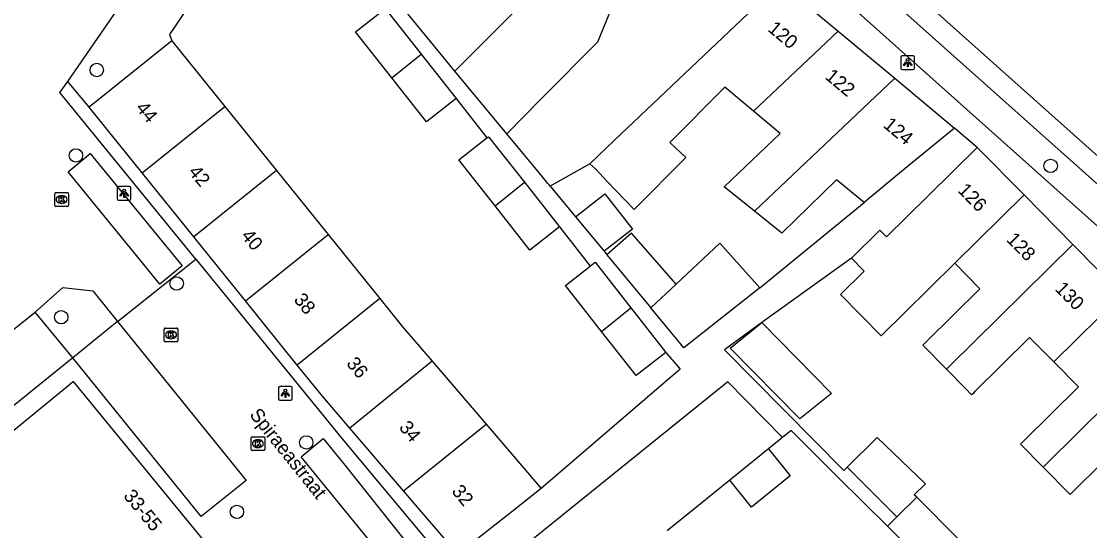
# Model space of a CAD drawing. Extents: x 161882 to 162509, y 381687 to 382379.
# Drawn here: x 162177.6 to 162255.4, y 382032.1 to 382069.2 of the extents above; entities that cross this region are included whole.
import ezdxf

# ---------------------------------------------------------------- set-up
doc = ezdxf.new("R2010")
doc.units = 0
for name, color, linetype in [('IMGEO_Boom', 7, 'Continuous'), ('IMGEO_Haag', 7, 'Continuous'), ('IMGEO_Kolk', 7, 'Continuous'), ('IMGEO_Lichtpunt', 7, 'Continuous'), ('IMGEO_Openbare_ruimte_label', 7, 'Continuous'), ('IMGEO_Pand', 7, 'Continuous'), ('IMGEO_Pand_nummerreeks', 7, 'Continuous'), ('IMGEO_Parkeervlak_open', 7, 'Continuous'), ('IMGEO_Rijbaan_lokaal_gesloten', 7, 'Continuous'), ('IMGEO_Rijbaan_lokaal_open', 7, 'Continuous'), ('IMGEO_Voetpad_open', 7, 'Continuous'), ('IMGEO_Woonerf_open', 7, 'Continuous')]:
    doc.layers.add(name, color=color, linetype=linetype)

msp = doc.modelspace()

# ---------------------------------------------------------------- linework, layer by layer
at = {"layer": 'IMGEO_Boom'}
for centre in [(162183.068, 382065.693), (162181.549, 382059.465), (162252.559, 382058.707), (162188.889, 382050.134), (162180.48, 382047.676), (162198.331, 382038.553), (162193.28, 382033.486)]:
    msp.add_circle(centre, 0.489, dxfattribs=at)
at = {"layer": 'IMGEO_Haag'}
for points in [[(162192.04, 382073.726), (162188.366, 382068.285), (162188.533, 382067.832)], [(162182.522, 382062.989), (162180.952, 382064.864)]]:
    msp.add_lwpolyline(points, dxfattribs=at)
at = {"layer": 'IMGEO_Kolk'}
for p, q in [((162180.005, 382055.829), (162180.005, 382056.681)), ((162180.08, 382056.755), (162180.932, 382056.755)), ((162180.493, 382056.535), (162180.518, 382056.535)), ((162181.006, 382056.681), (162181.006, 382055.829)), ((162180.932, 382055.755), (162180.08, 382055.755)), ((162180.516, 382055.975), (162180.491, 382055.975)), ((162187.978, 382045.964), (162187.978, 382046.816)), ((162188.053, 382046.89), (162188.905, 382046.89)), ((162188.466, 382046.67), (162188.491, 382046.67)), ((162188.979, 382046.816), (162188.979, 382045.964)), ((162188.905, 382045.89), (162188.053, 382045.89)), ((162188.489, 382046.11), (162188.464, 382046.11)), ((162194.307, 382038.036), (162194.307, 382038.888)), ((162194.382, 382038.962), (162195.234, 382038.962)), ((162194.795, 382038.742), (162194.82, 382038.742)), ((162195.308, 382038.888), (162195.308, 382038.036)), ((162195.234, 382037.962), (162194.382, 382037.962)), ((162194.818, 382038.182), (162194.793, 382038.182))]:
    msp.add_line(p, q, dxfattribs=at)
for points in [[(162180.005, 382055.829), (162180.005, 382056.681)], [(162180.08, 382056.755), (162180.932, 382056.755)], [(162180.326, 382056.455), (162180.449, 382056.455), (162180.449, 382056.304), (162180.579, 382056.455), (162180.743, 382056.455), (162180.597, 382056.304), (162180.75, 382056.055), (162180.598, 382056.055), (162180.513, 382056.219), (162180.449, 382056.152), (162180.449, 382056.055), (162180.326, 382056.055), (162180.326, 382056.455)], [(162181.006, 382056.681), (162181.006, 382055.829)], [(162180.932, 382055.755), (162180.08, 382055.755)], [(162187.978, 382045.964), (162187.978, 382046.816)], [(162188.053, 382046.89), (162188.905, 382046.89)], [(162188.299, 382046.59), (162188.422, 382046.59), (162188.422, 382046.439), (162188.552, 382046.59), (162188.716, 382046.59), (162188.57, 382046.439), (162188.723, 382046.19), (162188.571, 382046.19), (162188.486, 382046.354), (162188.422, 382046.287), (162188.422, 382046.19), (162188.299, 382046.19), (162188.299, 382046.59)], [(162188.979, 382046.816), (162188.979, 382045.964)], [(162188.905, 382045.89), (162188.053, 382045.89)], [(162194.307, 382038.036), (162194.307, 382038.888)], [(162194.382, 382038.962), (162195.234, 382038.962)], [(162194.628, 382038.662), (162194.751, 382038.662), (162194.751, 382038.511), (162194.881, 382038.662), (162195.045, 382038.662), (162194.899, 382038.511), (162195.052, 382038.262), (162194.9, 382038.262), (162194.815, 382038.426), (162194.751, 382038.359), (162194.751, 382038.262), (162194.628, 382038.262), (162194.628, 382038.662)], [(162195.308, 382038.888), (162195.308, 382038.036)], [(162195.234, 382037.962), (162194.382, 382037.962)]]:
    msp.add_lwpolyline(points, dxfattribs=at)
for centre, start, end in [((162180.082, 382056.679), 91.55205, 178.44795), ((162180.082, 382056.679), 91.55205, 178.44795), ((162180.93, 382056.679), 1.55205, 88.44795), ((162180.93, 382056.679), 1.55205, 88.44795), ((162180.082, 382055.831), 181.55205, 268.44795), ((162180.082, 382055.831), 181.55205, 268.44795), ((162180.93, 382055.831), 271.55205, 358.44795), ((162180.93, 382055.831), 271.55205, 358.44795), ((162188.055, 382046.814), 91.55205, 178.44795), ((162188.055, 382046.814), 91.55205, 178.44795), ((162188.903, 382046.814), 1.55205, 88.44795), ((162188.903, 382046.814), 1.55205, 88.44795), ((162188.055, 382045.966), 181.55205, 268.44795), ((162188.055, 382045.966), 181.55205, 268.44795), ((162188.903, 382045.966), 271.55205, 358.44795), ((162188.903, 382045.966), 271.55205, 358.44795), ((162194.384, 382038.886), 91.55205, 178.44795), ((162194.384, 382038.886), 91.55205, 178.44795), ((162195.232, 382038.886), 1.55205, 88.44795), ((162195.232, 382038.886), 1.55205, 88.44795), ((162194.384, 382038.038), 181.55205, 268.44795), ((162194.384, 382038.038), 181.55205, 268.44795), ((162195.232, 382038.038), 271.55205, 358.44795), ((162195.232, 382038.038), 271.55205, 358.44795)]:
    msp.add_arc(centre, 0.0765, start, end, dxfattribs=at)
for centre, major_axis, ratio, start_param, end_param in [((162180.492, 382056.255), (-0.387, 0.002), 0.722429, 4.712389, 7.853982), ((162180.517, 382056.255), (-0.39, 0.002), 0.717154, 1.570796, 4.712389), ((162188.465, 382046.39), (-0.387, 0.002), 0.722429, 4.712389, 7.853982), ((162188.49, 382046.39), (-0.39, 0.002), 0.717154, 1.570796, 4.712389), ((162194.794, 382038.462), (-0.387, 0.002), 0.722429, 4.712389, 7.853982), ((162194.819, 382038.462), (-0.39, 0.002), 0.717154, 1.570796, 4.712389)]:
    msp.add_ellipse(centre, major_axis=major_axis, ratio=ratio, start_param=start_param, end_param=end_param, dxfattribs=at)
at = {"layer": 'IMGEO_Lichtpunt'}
for p, q in [((162241.646, 382066.636), (162241.646, 382065.829)), ((162241.646, 382066.636), (162241.646, 382065.829)), ((162242.548, 382066.731), (162241.74, 382066.731)), ((162242.548, 382066.731), (162241.74, 382066.731)), ((162242.642, 382065.829), (162242.642, 382066.636)), ((162242.642, 382065.829), (162242.642, 382066.636)), ((162241.74, 382065.735), (162242.548, 382065.735)), ((162241.74, 382065.735), (162242.548, 382065.735)), ((162184.562, 382057.119), (162184.562, 382056.312)), ((162184.562, 382057.119), (162184.562, 382056.312)), ((162185.464, 382057.214), (162184.656, 382057.214)), ((162185.464, 382057.214), (162184.656, 382057.214)), ((162185.558, 382056.312), (162185.558, 382057.119)), ((162185.558, 382056.312), (162185.558, 382057.119)), ((162184.656, 382056.218), (162185.464, 382056.218)), ((162184.656, 382056.218), (162185.464, 382056.218)), ((162196.307, 382042.538), (162196.307, 382041.731)), ((162196.307, 382042.538), (162196.307, 382041.731)), ((162197.209, 382042.633), (162196.401, 382042.633)), ((162197.209, 382042.633), (162196.401, 382042.633)), ((162197.303, 382041.731), (162197.303, 382042.538)), ((162197.303, 382041.731), (162197.303, 382042.538)), ((162196.401, 382041.637), (162197.209, 382041.637)), ((162196.401, 382041.637), (162197.209, 382041.637))]:
    msp.add_line(p, q, dxfattribs=at)
for points in [[(162242.02, 382066.3), (162242.059, 382066.272), (162241.871, 382066.01), (162241.833, 382066.037), (162242.02, 382066.3)], [(162242.122, 382066.252), (162242.169, 382066.252), (162242.169, 382065.93), (162242.122, 382065.93), (162242.122, 382066.252)], [(162242.232, 382066.272), (162242.27, 382066.299), (162242.457, 382066.037), (162242.418, 382066.009), (162242.232, 382066.272)], [(162184.936, 382056.783), (162184.975, 382056.755), (162184.787, 382056.493), (162184.749, 382056.52), (162184.936, 382056.783)], [(162185.038, 382056.735), (162185.085, 382056.735), (162185.085, 382056.413), (162185.038, 382056.413), (162185.038, 382056.735)], [(162185.148, 382056.755), (162185.186, 382056.782), (162185.373, 382056.52), (162185.334, 382056.492), (162185.148, 382056.755)], [(162196.681, 382042.202), (162196.72, 382042.174), (162196.532, 382041.912), (162196.494, 382041.939), (162196.681, 382042.202)], [(162196.783, 382042.154), (162196.83, 382042.154), (162196.83, 382041.832), (162196.783, 382041.832), (162196.783, 382042.154)], [(162196.893, 382042.174), (162196.931, 382042.201), (162197.118, 382041.939), (162197.079, 382041.911), (162196.893, 382042.174)]]:
    msp.add_lwpolyline(points, dxfattribs=at)
for centre in [(162242.145, 382066.434), (162185.061, 382056.917), (162196.806, 382042.336)]:
    msp.add_circle(centre, 0.0994, dxfattribs=at)
for centre, start, end in [((162241.74, 382066.636), 90, 180), ((162241.74, 382066.636), 90, 180), ((162242.548, 382066.636), 0, 90), ((162242.548, 382066.636), 0, 90), ((162241.74, 382065.829), 180, 270), ((162241.74, 382065.829), 180, 270), ((162242.548, 382065.829), 270, 0), ((162242.548, 382065.829), 270, 360), ((162184.656, 382057.119), 90, 180), ((162184.656, 382057.119), 90, 180), ((162185.464, 382057.119), 0, 90), ((162185.464, 382057.119), 0, 90), ((162184.656, 382056.312), 180, 270), ((162184.656, 382056.312), 180, 270), ((162185.464, 382056.312), 270, 0), ((162185.464, 382056.312), 270, 360), ((162196.401, 382042.538), 90, 180), ((162196.401, 382042.538), 90, 180), ((162197.209, 382042.538), 0, 90), ((162197.209, 382042.538), 0, 90), ((162196.401, 382041.731), 180, 270), ((162196.401, 382041.731), 180, 270), ((162197.209, 382041.731), 270, 0), ((162197.209, 382041.731), 270, 360)]:
    msp.add_arc(centre, 0.0946, start, end, dxfattribs=at)
at = {"layer": 'IMGEO_Pand'}
for points in [[(162227.189, 382076.778), (162220.753, 382070.695), (162219.549, 382067.718), (162215.475, 382063.613), (162212.93, 382061.048)], [(162218.985, 382058.849), (162220.777, 382060.586), (162232.86, 382072.05)], [(162232.86, 382072.05), (162237.086, 382068.526)], [(162204.556, 382065.133), (162201.927, 382068.48), (162203.993, 382070.102)], [(162203.993, 382070.102), (162204.088, 382070.177), (162206.696, 382066.855)], [(162209.162, 382065.599), (162213.419, 382069.889), (162213.22, 382070.052)], [(162230.913, 382062.691), (162237.086, 382068.526)], [(162237.086, 382068.526), (162241.208, 382065.089)], [(162188.533, 382067.832), (162182.522, 382062.989)], [(162188.533, 382067.832), (162191.67, 382063.938), (162192.392, 382063.042)], [(162204.556, 382065.133), (162206.696, 382066.855)], [(162206.696, 382066.855), (162209.241, 382063.613)], [(162209.241, 382063.613), (162207.081, 382061.916), (162204.556, 382065.133)], [(162212.93, 382061.048), (162209.162, 382065.599)], [(162241.208, 382065.089), (162230.976, 382055.418)], [(162241.208, 382065.089), (162245.562, 382061.459)], [(162230.913, 382062.691), (162228.818, 382064.441), (162224.824, 382060.416), (162225.979, 382059.319), (162222.207, 382055.519), (162220.253, 382057.58), (162219.417, 382058.461), (162218.985, 382058.849)], [(162186.377, 382058.203), (162182.522, 382062.989)], [(162186.377, 382058.203), (162192.392, 382063.042)], [(162192.392, 382063.042), (162196.155, 382058.372)], [(162230.976, 382055.418), (162228.779, 382057.187), (162232.846, 382061.077), (162230.913, 382062.691)], [(162216.094, 382057.226), (162216.015, 382057.322), (162215.924, 382057.431), (162215.537, 382057.899), (162215.316, 382058.166), (162212.93, 382061.048)], [(162245.562, 382061.459), (162241.696, 382058.289), (162238.965, 382056.049)], [(162212.084, 382055.788), (162209.454, 382059.138), (162211.495, 382060.741)], [(162211.495, 382060.741), (162211.615, 382060.835), (162214.225, 382057.51)], [(162238.045, 382051.975), (162240.126, 382054.029), (162240.609, 382053.54), (162243.642, 382056.535), (162247.199, 382060.048)], [(162247.199, 382060.048), (162250.618, 382056.586)], [(162218.985, 382058.849), (162216.094, 382057.226)], [(162190.141, 382053.532), (162186.377, 382058.203)], [(162196.155, 382058.372), (162190.141, 382053.532)], [(162196.155, 382058.372), (162199.919, 382053.701)], [(162212.084, 382055.788), (162214.225, 382057.51)], [(162214.225, 382057.51), (162216.768, 382054.271)], [(162238.965, 382056.049), (162236.966, 382057.695), (162232.974, 382053.81), (162230.976, 382055.418)], [(162217.947, 382054.988), (162220.076, 382056.66), (162222.087, 382054.098), (162220.025, 382052.479)], [(162245.577, 382051.607), (162250.618, 382056.586)], [(162250.618, 382056.586), (162254.178, 382052.979)], [(162216.768, 382054.271), (162214.608, 382052.574), (162212.084, 382055.788)], [(162217.947, 382054.988), (162220.025, 382052.479)], [(162193.904, 382048.861), (162190.141, 382053.532)], [(162193.904, 382048.861), (162199.919, 382053.701)], [(162199.919, 382053.701), (162203.682, 382049.03)], [(162225.266, 382050.079), (162222.026, 382053.8), (162220.228, 382052.234)], [(162225.266, 382050.079), (162228.467, 382053.072), (162231.368, 382049.829)], [(162254.178, 382052.979), (162245.211, 382044.122), (162244.965, 382043.879)], [(162254.178, 382052.979), (162257.773, 382049.338)], [(162219.02, 382051.404), (162219.369, 382051.678), (162221.978, 382048.355)], [(162220.228, 382052.234), (162223.433, 382048.364)], [(162245.577, 382051.607), (162241.948, 382048.023), (162240.216, 382046.312), (162237.238, 382049.328), (162238.97, 382051.039), (162238.045, 382051.975)], [(162219.837, 382046.633), (162217.208, 382049.981), (162219.02, 382051.404)], [(162244.965, 382043.879), (162243.238, 382045.629), (162243.484, 382045.872), (162247.41, 382049.749), (162245.577, 382051.607)], [(162223.433, 382048.364), (162225.266, 382050.079)], [(162231.368, 382049.829), (162225.845, 382045.451), (162225.722, 382045.6), (162225.543, 382045.816), (162224.944, 382046.539), (162223.433, 382048.364)], [(162257.773, 382049.338), (162252.789, 382044.416)], [(162197.666, 382044.191), (162193.904, 382048.861)], [(162203.682, 382049.03), (162197.666, 382044.191)], [(162203.682, 382049.03), (162205.337, 382046.976), (162207.498, 382044.466)], [(162219.837, 382046.633), (162221.978, 382048.355)], [(162221.978, 382048.355), (162224.522, 382045.114)], [(162231.509, 382047.284), (162236.594, 382042.124), (162234.298, 382040.27), (162229.213, 382045.43), (162231.509, 382047.284)], [(162224.522, 382045.114), (162222.362, 382043.417), (162219.837, 382046.633)], [(162252.789, 382044.416), (162251.03, 382046.197), (162247.046, 382042.264), (162246.884, 382042.104), (162246.799, 382042.02), (162246.373, 382042.452), (162244.965, 382043.879)], [(162252.003, 382036.747), (162252.282, 382037.023), (162261.218, 382045.85)], [(162201.503, 382039.579), (162199.503, 382041.911), (162197.666, 382044.191)], [(162207.498, 382044.466), (162201.503, 382039.579)], [(162207.498, 382044.466), (162211.436, 382039.873)], [(162252.003, 382036.747), (162250.353, 382038.418), (162250.632, 382038.694), (162254.585, 382042.597), (162252.789, 382044.416)], [(162152.462, 382018.996), (162166.618, 382030.597), (162166.459, 382030.79), (162181.344, 382042.988), (162191.177, 382030.989), (162192.732, 382029.062), (162193.295, 382028.375), (162193.718, 382027.859)], [(162233.036, 382038.902), (162229.038, 382042.959), (162214.086, 382030.889), (162210.195, 382027.748)], [(162205.408, 382035.023), (162201.503, 382039.579)], [(162205.408, 382035.023), (162211.436, 382039.873)], [(162211.436, 382039.873), (162215.442, 382035.2)], [(162233.036, 382038.902), (162232.015, 382038.078)], [(162242.804, 382034.555), (162242.623, 382034.737), (162243.451, 382035.526), (162239.926, 382038.901), (162237.736, 382036.738)], [(162259.68, 382037.398), (162258.19, 382038.907), (162254.256, 382035.024), (162254.089, 382034.859), (162253.977, 382034.748), (162252.003, 382036.747)], [(162232.015, 382038.078), (162233.591, 382036.119), (162230.766, 382033.839), (162229.19, 382035.797)], [(162232.015, 382038.078), (162229.19, 382035.797)], [(162237.736, 382036.738), (162241.361, 382033.13)], [(162229.19, 382035.797), (162224.622, 382032.11)], [(162209.375, 382030.397), (162205.408, 382035.023)], [(162215.442, 382035.2), (162213.296, 382033.501), (162209.375, 382030.397)], [(162242.804, 382034.555), (162241.361, 382033.13)], [(162245.842, 382031.505), (162242.804, 382034.555)], [(162241.361, 382033.13), (162240.668, 382032.445)], [(162243.563, 382029.562), (162240.668, 382032.445)]]:
    msp.add_lwpolyline(points, dxfattribs=at)
at = {"layer": 'IMGEO_Parkeervlak_open'}
for points in [[(162182.598, 382059.604), (162189.283, 382051.419), (162187.664, 382050.096), (162186.507, 382051.513), (162180.979, 382058.281), (162182.598, 382059.604)], [(162149.021, 382018.603), (162146.162, 382022.187), (162178.575, 382048.051)], [(162181.319, 382044.718), (162178.575, 382048.051)], [(162184.589, 382047.362), (162181.319, 382044.718)]]:
    msp.add_lwpolyline(points, dxfattribs=at)
at = {"layer": 'IMGEO_Rijbaan_lokaal_gesloten'}
for points in [[(162208.443, 382099.25), (162241.416, 382072.435), (162262.315, 382053.78), (162275.851, 382040.075), (162276.287, 382039.572), (162328.522, 381979.28), (162327.205, 381978.154)], [(162271.925, 382041.627), (162261.12, 382052.791), (162240.386, 382071.297), (162229.73, 382079.712), (162208.292, 382097.099)]]:
    msp.add_lwpolyline(points, dxfattribs=at)
at = {"layer": 'IMGEO_Rijbaan_lokaal_open'}
for points in [[(162184.589, 382047.362), (162190.279, 382051.904)], [(162190.279, 382051.904), (162200.94, 382038.82), (162208.554, 382029.711)], [(162184.589, 382047.362), (162193.949, 382035.786), (162190.679, 382033.142), (162181.319, 382044.718)], [(162181.319, 382044.718), (162149.021, 382018.603)], [(162205.956, 382027.701), (162197.948, 382037.505), (162199.568, 382038.828), (162201.169, 382036.868), (162214.404, 382020.232), (162227.861, 382003.318), (162240.04, 381988.01)]]:
    msp.add_lwpolyline(points, dxfattribs=at)
at = {"layer": 'IMGEO_Voetpad_open'}
for points in [[(162269.744, 382040.83), (162259.121, 382051.495), (162238.764, 382069.685), (162230.249, 382076.62)], [(162209.162, 382065.599), (162202.184, 382074.144)], [(162209.241, 382063.613), (162211.495, 382060.741)], [(162247.199, 382060.048), (162245.562, 382061.459)], [(162216.094, 382057.226), (162217.947, 382054.988)], [(162231.368, 382049.829), (162238.965, 382056.049)], [(162216.768, 382054.271), (162219.02, 382051.404)], [(162220.025, 382052.479), (162220.228, 382052.234)], [(162238.045, 382051.975), (162231.509, 382047.284)], [(162231.509, 382047.284), (162228.803, 382045.309), (162237.498, 382036.504), (162237.736, 382036.738)], [(162224.522, 382045.114), (162225.575, 382043.886), (162215.442, 382035.2)], [(162240.668, 382032.445), (162237.043, 382036.054), (162233.665, 382039.41), (162233.036, 382038.902)]]:
    msp.add_lwpolyline(points, dxfattribs=at)
at = {"layer": 'IMGEO_Woonerf_open'}
for points in [[(162180.952, 382064.864), (162188.641, 382076.009)], [(162190.279, 382051.904), (162180.387, 382064.044), (162180.952, 382064.864)], [(162178.575, 382048.051), (162180.597, 382049.844), (162182.771, 382049.594), (162184.589, 382047.362)]]:
    msp.add_lwpolyline(points, dxfattribs=at)

# ---------------------------------------------------------------- texts
at = {"layer": 'IMGEO_Openbare_ruimte_label'}
msp.add_text('Spiraeastraat', height=1, rotation=308.624, dxfattribs=at).set_placement((162194.15, 382040.555))
at = {"layer": 'IMGEO_Pand_nummerreeks'}
for s, rotation, p in [('120', 320.17943, (162231.887, 382068.591)), ('122', 320.17786, (162236.057, 382065.114)), ('44', 309.48558, (162185.859, 382062.902)), ('124', 320.17786, (162240.296, 382061.58)), ('42', 309.48558, (162189.693, 382058.248)), ('126', 314.6332, (162245.731, 382056.866)), ('40', 309.48558, (162193.534, 382053.587)), ('128', 314.6332, (162249.275, 382053.276)), ('130', 314.6332, (162252.816, 382049.689)), ('38', 309.48558, (162197.37, 382048.931)), ('36', 309.48804, (162201.204, 382044.277)), ('34', 309.48558, (162205.04, 382039.622)), ('32', 309.48558, (162208.874, 382034.968)), ('33-55', 309.33334, (162184.964, 382034.627))]:
    msp.add_text(s, height=1, rotation=rotation, dxfattribs=at).set_placement(p)

doc.saveas('drawing.dxf')
